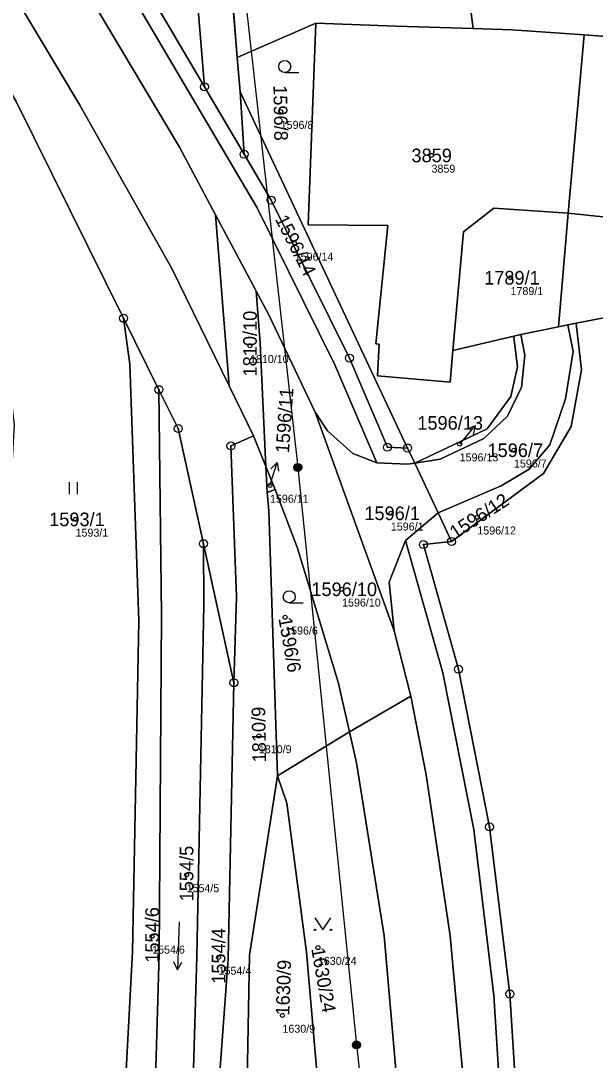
# Model space of a CAD drawing. Extents: x -653098 to -649479, y -997642 to -992666.
# Drawn here: x -650604.2 to -650532.3, y -996480.3 to -996350.3 of the extents above; entities that cross this region are included whole.
import ezdxf

# ---------------------------------------------------------------- set-up
doc = ezdxf.new("R2010")
doc.units = 0
for name, color, linetype in [('Definiční body', 7, 'Continuous'), ('Hranice parcel', 7, 'Continuous'), ('Parcelní čísla', 7, 'Continuous'), ('Polygon parcely', 7, 'Continuous'), ('Pop  PČ popisy', 7, 'Continuous'), ('Poz předměty', 7, 'Continuous'), ('Značky bodu BP', 7, 'Continuous'), ('Značky kultur', 7, 'Continuous')]:
    doc.layers.add(name, color=color, linetype=linetype)

msp = doc.modelspace()

# ---------------------------------------------------------------- linework, layer by layer
at = {"layer": 'Definiční body'}
for centre in [(-650571.66, -996361.69), (-650552.79, -996367.17), (-650569.9, -996378.16), (-650542.91, -996382.46), (-650575.5, -996390.96), (-650549.27, -996403.25), (-650542.48, -996404.02), (-650573, -996408.42), (-650597.32, -996412.66), (-650557.88, -996411.9), (-650547.06, -996412.39), (-650563.98, -996421.4), (-650571.1, -996424.9), (-650574.39, -996439.73), (-650583.43, -996457.1), (-650587.74, -996464.78), (-650567, -996466.19), (-650579.43, -996467.41), (-650571.44, -996474.67)]:
    msp.add_circle(centre, 0.25, dxfattribs=at)
at = {"layer": 'Hranice parcel'}
for p, q in [((-650554.94, -996294.79), (-650547.58, -996351.32)), ((-650581.76, -996297.58), (-650577.09, -996354.94)), ((-650587.29, -996348.25), (-650581.19, -996358.59)), ((-650567.26, -996350.65), (-650577.09, -996354.94)), ((-650533.69, -996352.11), (-650535.68, -996374.38)), ((-650533.69, -996352.11), (-650508.63, -996353.93)), ((-650577.09, -996354.94), (-650576.74, -996359.23)), ((-650581.19, -996358.59), (-650576.23, -996367.02)), ((-650576.23, -996367.02), (-650576.74, -996359.23)), ((-650576.74, -996359.23), (-650555.79, -996403.74)), ((-650578.11, -996395.96), (-650579.83, -996374.59)), ((-650536.9, -996388.58), (-650535.68, -996374.38)), ((-650535.68, -996374.38), (-650509.6, -996377.15)), ((-650586.89, -996396.45), (-650591.31, -996387.53)), ((-650535.73, -996388.34), (-650534.69, -996388.12)), ((-650536.9, -996388.58), (-650541.61, -996389.55)), ((-650535.73, -996388.34), (-650536.9, -996388.58)), ((-650542.51, -996389.75), (-650550.13, -996391.56)), ((-650542.51, -996389.75), (-650541.61, -996389.55)), ((-650578.11, -996395.96), (-650575.06, -996402.22)), ((-650567.34, -996399.26), (-650557.46, -996426.59)), ((-650575.06, -996402.22), (-650573.52, -996406.04)), ((-650555.79, -996403.74), (-650554.9, -996405.62)), ((-650573.52, -996406.04), (-650572.35, -996408.91)), ((-650573.52, -996406.04), (-650573.35, -996409.31)), ((-650551.97, -996411.84), (-650554.9, -996405.62)), ((-650572.35, -996408.91), (-650573.35, -996409.31)), ((-650556.03, -996415.31), (-650551.97, -996411.84)), ((-650550.29, -996415.42), (-650551.97, -996411.84)), ((-650581.32, -996415.7), (-650577.51, -996433.09)), ((-650555.4, -996434.75), (-650557.46, -996426.59)), ((-650555.4, -996434.75), (-650563.06, -996439.2)), ((-650572.05, -996444.71), (-650563.06, -996439.2))]:
    msp.add_line(p, q, dxfattribs=at)
for points in [[(-650575.37, -995959.87), (-650608.41, -995944), (-650610.43, -995943.86), (-650611.96, -995945.87), (-650628.76, -995975.13), (-650648.35, -996007.09), (-650662.99, -996034.56), (-650671.68, -996054.53), (-650676.6, -996068.37), (-650679.44, -996078.12), (-650683.79, -996097.9), (-650686.06, -996119.41), (-650686.27, -996132.3), (-650684.64, -996153.85), (-650680.81, -996173.83), (-650676.67, -996188.65), (-650668.33, -996210.53), (-650657.86, -996232.42), (-650644.24, -996256.86), (-650595.14, -996338.86), (-650574.61, -996373.71), (-650564.87, -996393.33), (-650559.65, -996405.6)], [(-650579.83, -996374.59), (-650584.33, -996366.13), (-650603.23, -996334.38), (-650640.77, -996271.85), (-650662.24, -996233.94), (-650673.04, -996211.24), (-650681.26, -996189.41), (-650687.35, -996165.84), (-650690.42, -996143.11), (-650690.64, -996118.19), (-650688.08, -996095.67), (-650683.42, -996075.21), (-650681.92, -996070.45)], [(-650591.31, -996387.53), (-650604.76, -996360.43), (-650648.92, -996285.46), (-650668.2, -996252.11), (-650678.11, -996231.78), (-650693.48, -996194.73), (-650701.11, -996158.83), (-650702.82, -996142.05), (-650703.55, -996130.09), (-650704.38, -996128.54)], [(-650699.56, -996129.85), (-650698.84, -996141.72), (-650697.15, -996158.23), (-650692.97, -996178.61), (-650686.91, -996198.66), (-650678.39, -996219.51), (-650663, -996249.61), (-650638.21, -996291.69), (-650596.8, -996360.89), (-650585.26, -996381.29), (-650578.11, -996395.96)], [(-650581.19, -996358.59), (-650582.63, -996340.7), (-650586.6, -996298.44)], [(-650550.13, -996391.56), (-650550.45, -996395.52), (-650559.53, -996394.71), (-650559.35, -996390.75), (-650559.75, -996390.72), (-650558.26, -996375.92), (-650568.24, -996375.83), (-650567.26, -996350.65)], [(-650567.26, -996350.65), (-650557.21, -996351.03), (-650547.58, -996351.32)], [(-650547.58, -996351.32), (-650542.76, -996351.46), (-650533.69, -996352.11)], [(-650576.23, -996367.02), (-650572.85, -996372.76), (-650563.06, -996392.5), (-650558.31, -996403.65), (-650555.79, -996403.74)], [(-650535.68, -996374.38), (-650545, -996373.74), (-650548.8, -996376.73), (-650550.13, -996391.56)], [(-650574.73, -996384.14), (-650574.86, -996383.9), (-650579.83, -996374.59)], [(-650567.34, -996399.26), (-650573.19, -996387.03), (-650574.73, -996384.14)], [(-650574.73, -996384.14), (-650574.23, -996390.63), (-650573.52, -996406.04)], [(-650503.13, -996383.96), (-650509.86, -996384.68), (-650526.23, -996386.52), (-650534.69, -996388.12)], [(-650589.96, -996512.9), (-650591.82, -996502.17), (-650591.18, -996485.47), (-650590.2, -996466.72), (-650589.41, -996425.36), (-650590.51, -996393.26), (-650591.31, -996387.53)], [(-650534.69, -996388.12), (-650534.68, -996388.19), (-650534.04, -996393.96), (-650535.34, -996401.04), (-650538.78, -996406.94), (-650550.29, -996415.42)], [(-650551.97, -996411.84), (-650544.07, -996408.48), (-650540.59, -996406.37), (-650538, -996403.35), (-650536.05, -996397.61), (-650535.09, -996391.66), (-650535.73, -996388.34)], [(-650541.61, -996389.55), (-650541.11, -996392.13), (-650541.55, -996396.13), (-650543.3, -996399.74), (-650546.25, -996402.55), (-650551.7, -996405.13), (-650554.9, -996405.62)], [(-650554.9, -996405.62), (-650545.84, -996401.35), (-650542.89, -996397.32), (-650542.03, -996393.59), (-650542.49, -996389.9), (-650542.51, -996389.75)], [(-650586.89, -996396.45), (-650586.55, -996424.66), (-650586.84, -996466.96), (-650587.38, -996484.09), (-650588.2, -996502.26), (-650589.96, -996512.9)], [(-650581.32, -996415.7), (-650584.47, -996401.31), (-650586.89, -996396.45)], [(-650559.65, -996405.6), (-650562.63, -996404.44), (-650565.79, -996401.6), (-650567.34, -996399.26)], [(-650575.06, -996402.22), (-650577.88, -996403.47), (-650577.18, -996422.36), (-650577.51, -996433.09)], [(-650554.9, -996405.62), (-650555.81, -996405.74), (-650559.65, -996405.6)], [(-650563.06, -996439.2), (-650564.47, -996432.99), (-650569.57, -996416.28), (-650572.35, -996408.91)], [(-650573.35, -996409.31), (-650573.16, -996411.6), (-650572.05, -996444.71)], [(-650557.46, -996426.59), (-650558.07, -996420.5), (-650556.03, -996415.31)], [(-650481.95, -996618.06), (-650484.99, -996623.94), (-650491.46, -996628.69), (-650497.3, -996630.15), (-650503.13, -996629.04), (-650508.23, -996625.8), (-650513.58, -996619.75), (-650516.18, -996615.43), (-650526.52, -996590.48), (-650532.31, -996579.92), (-650535.84, -996568.82), (-650536.89, -996564.24), (-650538.64, -996553.86), (-650541.82, -996522.77), (-650544.98, -996472.17), (-650547.51, -996451.42), (-650551.36, -996431.86), (-650556.03, -996415.31)], [(-650550.29, -996415.42), (-650553.81, -996415.81), (-650549.42, -996431.4), (-650545.54, -996451.11), (-650542.99, -996471.99), (-650539.83, -996522.62), (-650536.66, -996553.58), (-650533.9, -996568.33), (-650530.47, -996579.13), (-650524.71, -996589.62), (-650514.09, -996615.3), (-650481.83, -996615.01)], [(-650587.45, -996520.47), (-650586.14, -996517.22), (-650583.65, -996508.75), (-650583.07, -996498.11), (-650582.16, -996467.3), (-650581.26, -996423.36), (-650581.32, -996415.7)], [(-650577.51, -996433.09), (-650578.22, -996467.58), (-650580.47, -996498.26), (-650580.71, -996502.46), (-650580.86, -996508.82), (-650581.91, -996521.13)], [(-650515.19, -996635.92), (-650515.74, -996634.98), (-650521.36, -996615.63), (-650527.52, -996600.48), (-650530.39, -996592.62), (-650536.34, -996584.16), (-650536.75, -996582.96), (-650541.65, -996564.02), (-650544.65, -996544.52), (-650546.28, -996524.74), (-650547.43, -996504.82), (-650548.64, -996484.79), (-650550.46, -996464.7), (-650553.47, -996444.6), (-650555.4, -996434.75)], [(-650563.06, -996439.2), (-650562.17, -996443.09), (-650558.72, -996464.73), (-650556.36, -996491.5)], [(-650572.05, -996444.71), (-650575.58, -996467.15), (-650575.92, -996487.33), (-650576.13, -996490.32)], [(-650566.65, -996490.88), (-650566.73, -996487.87), (-650566.77, -996486.05), (-650568.45, -996466.75), (-650570.87, -996448.12), (-650572.05, -996444.71)]]:
    msp.add_lwpolyline(points, dxfattribs=at)
at = {"layer": 'Polygon parcely'}
for points in [[(-650599.51, -996170.83), (-650604.08, -996171.11), (-650601.43, -996187.33), (-650590.92, -996299.38), (-650588.21, -996340.7), (-650587.29, -996348.25), (-650581.19, -996358.59), (-650582.63, -996340.7), (-650586.6, -996298.44), (-650597.07, -996187.91)], [(-650547.58, -996351.32), (-650554.94, -996294.79), (-650581.76, -996297.58), (-650577.09, -996354.94), (-650567.26, -996350.65), (-650557.21, -996351.03)], [(-650542.76, -996351.46), (-650533.69, -996352.11), (-650508.63, -996353.93), (-650551.45, -996299.47), (-650554.94, -996294.79), (-650547.58, -996351.32)], [(-650576.23, -996367.02), (-650576.74, -996359.23), (-650577.09, -996354.94), (-650581.76, -996297.58), (-650586.6, -996298.44), (-650582.63, -996340.7), (-650581.19, -996358.59)], [(-650542.49, -996389.9), (-650542.51, -996389.75), (-650550.13, -996391.56), (-650550.45, -996395.52), (-650559.53, -996394.71), (-650559.35, -996390.75), (-650559.75, -996390.72), (-650558.26, -996375.92), (-650568.24, -996375.83), (-650567.26, -996350.65), (-650577.09, -996354.94), (-650576.74, -996359.23), (-650555.79, -996403.74), (-650554.9, -996405.62), (-650545.84, -996401.35), (-650542.89, -996397.32), (-650542.03, -996393.59)], [(-650547.58, -996351.32), (-650557.21, -996351.03), (-650567.26, -996350.65), (-650568.24, -996375.83), (-650558.26, -996375.92), (-650559.75, -996390.72), (-650559.35, -996390.75), (-650559.53, -996394.71), (-650550.45, -996395.52), (-650550.13, -996391.56), (-650548.8, -996376.73), (-650545, -996373.74), (-650535.68, -996374.38), (-650533.69, -996352.11), (-650542.76, -996351.46)], [(-650509.6, -996377.15), (-650508.63, -996353.93), (-650533.69, -996352.11), (-650535.68, -996374.38)], [(-650534.69, -996388.12), (-650526.23, -996386.52), (-650509.86, -996384.68), (-650503.13, -996383.96), (-650483.36, -996381.86), (-650449.54, -996376.52), (-650448.6, -996369.71), (-650449.42, -996356.46), (-650463.33, -996369.25), (-650484.06, -996375.37), (-650502.17, -996376.51), (-650506.12, -996376.78), (-650509.6, -996377.15), (-650535.68, -996374.38), (-650536.9, -996388.58), (-650535.73, -996388.34)], [(-650576.23, -996367.02), (-650572.85, -996372.76), (-650563.06, -996392.5), (-650558.31, -996403.65), (-650555.79, -996403.74), (-650576.74, -996359.23)], [(-650541.61, -996389.55), (-650536.9, -996388.58), (-650535.68, -996374.38), (-650545, -996373.74), (-650548.8, -996376.73), (-650550.13, -996391.56), (-650542.51, -996389.75)], [(-650575.06, -996402.22), (-650573.52, -996406.04), (-650574.23, -996390.63), (-650574.73, -996384.14), (-650574.86, -996383.9), (-650579.83, -996374.59), (-650578.11, -996395.96)], [(-650574.73, -996384.14), (-650574.23, -996390.63), (-650573.52, -996406.04), (-650572.35, -996408.91), (-650569.57, -996416.28), (-650564.47, -996432.99), (-650563.06, -996439.2), (-650555.4, -996434.75), (-650557.46, -996426.59), (-650567.34, -996399.26), (-650573.19, -996387.03)], [(-650591.31, -996387.53), (-650590.51, -996393.26), (-650589.41, -996425.36), (-650590.2, -996466.72), (-650591.18, -996485.47), (-650591.82, -996502.17), (-650589.96, -996512.9), (-650588.2, -996502.26), (-650587.38, -996484.09), (-650586.84, -996466.96), (-650586.55, -996424.66), (-650586.89, -996396.45)], [(-650551.97, -996411.84), (-650550.29, -996415.42), (-650538.78, -996406.94), (-650535.34, -996401.04), (-650534.04, -996393.96), (-650534.68, -996388.19), (-650534.69, -996388.12), (-650535.73, -996388.34), (-650535.09, -996391.66), (-650536.05, -996397.61), (-650538, -996403.35), (-650540.59, -996406.37), (-650544.07, -996408.48)], [(-650535.73, -996388.34), (-650536.9, -996388.58), (-650541.61, -996389.55), (-650541.11, -996392.13), (-650541.55, -996396.13), (-650543.3, -996399.74), (-650546.25, -996402.55), (-650551.7, -996405.13), (-650554.9, -996405.62), (-650551.97, -996411.84), (-650544.07, -996408.48), (-650540.59, -996406.37), (-650538, -996403.35), (-650536.05, -996397.61), (-650535.09, -996391.66)], [(-650541.61, -996389.55), (-650542.51, -996389.75), (-650542.49, -996389.9), (-650542.03, -996393.59), (-650542.89, -996397.32), (-650545.84, -996401.35), (-650554.9, -996405.62), (-650551.7, -996405.13), (-650546.25, -996402.55), (-650543.3, -996399.74), (-650541.55, -996396.13), (-650541.11, -996392.13)], [(-650583.65, -996508.75), (-650583.07, -996498.11), (-650582.16, -996467.3), (-650581.26, -996423.36), (-650581.32, -996415.7), (-650584.47, -996401.31), (-650586.89, -996396.45), (-650586.55, -996424.66), (-650586.84, -996466.96), (-650587.38, -996484.09), (-650588.2, -996502.26), (-650589.96, -996512.9), (-650606.14, -996543.16), (-650606.53, -996546.22), (-650599.96, -996558.72), (-650590.92, -996529.08), (-650587.45, -996520.47), (-650586.14, -996517.22)], [(-650557.46, -996426.59), (-650558.07, -996420.5), (-650556.03, -996415.31), (-650551.97, -996411.84), (-650554.9, -996405.62), (-650555.81, -996405.74), (-650559.65, -996405.6), (-650562.63, -996404.44), (-650565.79, -996401.6), (-650567.34, -996399.26)], [(-650573.52, -996406.04), (-650573.35, -996409.31), (-650572.35, -996408.91)], [(-650573.16, -996411.6), (-650572.05, -996444.71), (-650563.06, -996439.2), (-650564.47, -996432.99), (-650569.57, -996416.28), (-650572.35, -996408.91), (-650573.35, -996409.31)], [(-650581.91, -996521.13), (-650580.86, -996508.82), (-650580.71, -996502.46), (-650580.47, -996498.26), (-650578.22, -996467.58), (-650577.51, -996433.09), (-650581.32, -996415.7), (-650581.26, -996423.36), (-650582.16, -996467.3), (-650583.07, -996498.11), (-650583.65, -996508.75), (-650586.14, -996517.22), (-650587.45, -996520.47)], [(-650572.05, -996444.71), (-650570.87, -996448.12), (-650568.45, -996466.75), (-650566.77, -996486.05), (-650566.73, -996487.87), (-650566.65, -996490.88), (-650556.36, -996491.5), (-650558.72, -996464.73), (-650562.17, -996443.09), (-650563.06, -996439.2)], [(-650575.58, -996467.15), (-650575.92, -996487.33), (-650576.13, -996490.32), (-650566.65, -996490.88), (-650566.73, -996487.87), (-650566.77, -996486.05), (-650568.45, -996466.75), (-650570.87, -996448.12), (-650572.05, -996444.71)]]:
    msp.add_lwpolyline(points, close=True, dxfattribs=at)
for points in [[(-650632.09, -996321.67), (-650614.12, -996355.56), (-650607.05, -996384.1), (-650604.98, -996400.86), (-650606.16, -996421.63), (-650611.29, -996449.19), (-650617.21, -996488.51), (-650616.51, -996503.94), (-650615.64, -996515.14), (-650594.33, -996512.62), (-650589.96, -996512.9), (-650591.82, -996502.17), (-650591.18, -996485.47), (-650590.2, -996466.72), (-650589.41, -996425.36), (-650590.51, -996393.26), (-650591.31, -996387.53), (-650604.76, -996360.43), (-650648.92, -996285.46)], [(-650648.92, -996285.46), (-650604.76, -996360.43), (-650591.31, -996387.53), (-650586.89, -996396.45), (-650584.47, -996401.31), (-650581.32, -996415.7), (-650577.51, -996433.09), (-650577.18, -996422.36), (-650577.88, -996403.47), (-650575.06, -996402.22), (-650578.11, -996395.96), (-650585.26, -996381.29), (-650596.8, -996360.89), (-650638.21, -996291.69)], [(-650638.21, -996291.69), (-650596.8, -996360.89), (-650585.26, -996381.29), (-650578.11, -996395.96), (-650579.83, -996374.59), (-650584.33, -996366.13), (-650603.23, -996334.38)], [(-650603.23, -996334.38), (-650584.33, -996366.13), (-650579.83, -996374.59), (-650574.86, -996383.9), (-650574.73, -996384.14), (-650573.19, -996387.03), (-650567.34, -996399.26), (-650565.79, -996401.6), (-650562.63, -996404.44), (-650559.65, -996405.6), (-650564.87, -996393.33), (-650574.61, -996373.71), (-650595.14, -996338.86)], [(-650595.14, -996338.86), (-650574.61, -996373.71), (-650564.87, -996393.33), (-650559.65, -996405.6), (-650555.81, -996405.74), (-650554.9, -996405.62), (-650555.79, -996403.74), (-650558.31, -996403.65), (-650563.06, -996392.5), (-650572.85, -996372.76), (-650576.23, -996367.02), (-650581.19, -996358.59), (-650587.29, -996348.25)], [(-650526.23, -996386.52), (-650534.69, -996388.12), (-650534.68, -996388.19), (-650534.04, -996393.96), (-650535.34, -996401.04), (-650538.78, -996406.94), (-650550.29, -996415.42), (-650553.81, -996415.81), (-650549.42, -996431.4), (-650545.54, -996451.11), (-650542.99, -996471.99), (-650539.83, -996522.62), (-650536.66, -996553.58), (-650533.9, -996568.33)], [(-650575.92, -996487.33), (-650575.58, -996467.15), (-650572.05, -996444.71), (-650573.16, -996411.6), (-650573.35, -996409.31), (-650573.52, -996406.04), (-650575.06, -996402.22), (-650577.88, -996403.47), (-650577.18, -996422.36), (-650577.51, -996433.09), (-650578.22, -996467.58), (-650580.47, -996498.26)], [(-650533.9, -996568.33), (-650536.66, -996553.58), (-650539.83, -996522.62), (-650542.99, -996471.99), (-650545.54, -996451.11), (-650549.42, -996431.4), (-650553.81, -996415.81), (-650550.29, -996415.42), (-650551.97, -996411.84), (-650556.03, -996415.31), (-650551.36, -996431.86), (-650547.51, -996451.42), (-650544.98, -996472.17), (-650541.82, -996522.77), (-650538.64, -996553.86), (-650536.89, -996564.24), (-650535.84, -996568.82)], [(-650535.84, -996568.82), (-650536.89, -996564.24), (-650538.64, -996553.86), (-650541.82, -996522.77), (-650544.98, -996472.17), (-650547.51, -996451.42), (-650551.36, -996431.86), (-650556.03, -996415.31), (-650558.07, -996420.5), (-650557.46, -996426.59), (-650555.4, -996434.75), (-650553.47, -996444.6), (-650550.46, -996464.7), (-650548.64, -996484.79), (-650547.43, -996504.82), (-650546.28, -996524.74), (-650544.65, -996544.52), (-650541.65, -996564.02), (-650536.75, -996582.96)], [(-650536.75, -996582.96), (-650541.65, -996564.02), (-650544.65, -996544.52), (-650546.28, -996524.74), (-650547.43, -996504.82), (-650548.64, -996484.79), (-650550.46, -996464.7), (-650553.47, -996444.6), (-650555.4, -996434.75), (-650563.06, -996439.2), (-650562.17, -996443.09), (-650558.72, -996464.73), (-650556.36, -996491.5), (-650554.43, -996524.57), (-650552.38, -996548.84), (-650549.17, -996572.98)]]:
    msp.add_lwpolyline(points, dxfattribs=at)
at = {"layer": 'Pop  PČ popisy'}
for p, q in [((-650549.27, -996403.25), (-650547.34, -996400.95)), ((-650547.34, -996400.95), (-650548.37, -996401.4)), ((-650547.34, -996400.95), (-650547.6, -996402.04)), ((-650573, -996408.42), (-650572.12, -996405.55)), ((-650572.12, -996405.55), (-650572.89, -996406.36)), ((-650572.12, -996405.55), (-650571.94, -996406.65))]:
    msp.add_line(p, q, dxfattribs=at)
at = {"layer": 'Poz předměty'}
for p, q in [((-650577.17, -996338.07), (-650569.52, -996406.17)), ((-650569.52, -996406.17), (-650562.19, -996478.36)), ((-650562.19, -996478.36), (-650554.07, -996548.07))]:
    msp.add_line(p, q, dxfattribs=at)
for centre, radius in [((-650569.52, -996406.17), 0.5), ((-650569.52, -996406.17), 0.4), ((-650569.52, -996406.17), 0.3), ((-650569.52, -996406.17), 0.2), ((-650569.52, -996406.17), 0.1), ((-650562.19, -996478.36), 0.5), ((-650562.19, -996478.36), 0.4), ((-650562.19, -996478.36), 0.3), ((-650562.19, -996478.36), 0.2), ((-650562.19, -996478.36), 0.1)]:
    msp.add_circle(centre, radius, dxfattribs=at)
at = {"layer": 'Značky bodu BP'}
for centre, radius in [((-650581.19, -996358.59), 0.5), ((-650581.19, -996358.59), 0.0303), ((-650576.23, -996367.02), 0.5), ((-650576.23, -996367.02), 0.0303), ((-650572.85, -996372.76), 0.5), ((-650572.85, -996372.76), 0.0303), ((-650591.31, -996387.53), 0.5), ((-650591.31, -996387.53), 0.0303), ((-650563.06, -996392.5), 0.5), ((-650563.06, -996392.5), 0.0303), ((-650586.89, -996396.45), 0.5), ((-650586.89, -996396.45), 0.0303), ((-650584.47, -996401.31), 0.5), ((-650584.47, -996401.31), 0.0303), ((-650577.88, -996403.47), 0.5), ((-650577.88, -996403.47), 0.0303), ((-650558.31, -996403.65), 0.5), ((-650558.31, -996403.65), 0.0303), ((-650555.79, -996403.74), 0.5), ((-650555.79, -996403.74), 0.0303), ((-650581.32, -996415.7), 0.5), ((-650553.81, -996415.81), 0.5), ((-650550.29, -996415.42), 0.5), ((-650550.29, -996415.42), 0.0303), ((-650581.32, -996415.7), 0.0303), ((-650553.81, -996415.81), 0.0303), ((-650549.42, -996431.4), 0.5), ((-650549.42, -996431.4), 0.0303), ((-650577.51, -996433.09), 0.5), ((-650577.51, -996433.09), 0.0303), ((-650545.54, -996451.11), 0.5), ((-650545.54, -996451.11), 0.0303), ((-650542.99, -996471.99), 0.5), ((-650542.99, -996471.99), 0.0303)]:
    msp.add_circle(centre, radius, dxfattribs=at)
at = {"layer": 'Značky kultur'}
for p, q in [((-650571.15, -996356.8), (-650569.4, -996356.8)), ((-650598.06, -996409.51), (-650598.06, -996408.01)), ((-650597.06, -996409.51), (-650597.06, -996408.01)), ((-650570.59, -996423.08), (-650568.84, -996423.08)), ((-650584.36, -996462.96), (-650584.57, -996468.96)), ((-650584.57, -996468.96), (-650585.04, -996467.96)), ((-650584.57, -996468.96), (-650584.04, -996468))]:
    msp.add_line(p, q, dxfattribs=at)
msp.add_lwpolyline([(-650567.37, -996462.47), (-650566.37, -996463.97), (-650565.37, -996462.47)], dxfattribs=at)
for centre, radius in [((-650571.15, -996356.05), 0.75), ((-650570.59, -996422.33), 0.75), ((-650567.37, -996463.97), 0.1), ((-650565.37, -996463.97), 0.1)]:
    msp.add_circle(centre, radius, dxfattribs=at)

# ---------------------------------------------------------------- texts
at = {"layer": 'Definiční body'}
for s, p in [('1596/8', (-650571.66, -996363.85)), ('3859', (-650552.79, -996369.33)), ('1596/14', (-650569.9, -996380.32)), ('1789/1', (-650542.91, -996384.62)), ('1810/10', (-650575.5, -996393.12)), ('1596/13', (-650549.27, -996405.41)), ('1596/7', (-650542.48, -996406.18)), ('1596/11', (-650573, -996410.58)), ('1593/1', (-650597.32, -996414.82)), ('1596/1', (-650557.88, -996414.06)), ('1596/12', (-650547.06, -996414.55)), ('1596/10', (-650563.98, -996423.56)), ('1596/6', (-650571.1, -996427.06)), ('1810/9', (-650574.39, -996441.89)), ('1554/5', (-650583.43, -996459.26)), ('1554/6', (-650587.74, -996466.94)), ('1630/24', (-650567, -996468.35)), ('1554/4', (-650579.43, -996469.57)), ('1630/9', (-650571.44, -996476.83))]:
    msp.add_text(s, height=1, dxfattribs=at).set_placement(p)
at = {"layer": 'Parcelní čísla'}
for s, rotation, p in [('1596/8', 271, (-650572.57, -996358.4)), ('1596/14', 297, (-650572.4, -996375.13)), ('1810/10', 90, (-650574.65, -996394.8)), ('1596/11', 86, (-650570.62, -996404.44)), ('1596/12', 33, (-650549.82, -996415.19)), ('1596/6', 280, (-650571.94, -996425.05)), ('1810/9', 91, (-650573.48, -996443.02)), ('1554/5', 90, (-650582.58, -996460.41)), ('1554/6', 90, (-650586.89, -996468.08)), ('1554/4', 90, (-650578.58, -996470.71)), ('1630/24', 280, (-650567.84, -996466.34)), ('1630/9', 88, (-650570.59, -996474.7))]:
    msp.add_text(s, height=1.7, rotation=rotation, dxfattribs=at).set_placement(p)
for s, p in [('3859', (-650555.3, -996368.02)), ('1789/1', (-650546.21, -996383.31)), ('1596/13', (-650554.57, -996401.45)), ('1596/7', (-650545.79, -996404.87)), ('1596/1', (-650561.19, -996412.75)), ('1593/1', (-650600.62, -996413.51)), ('1596/10', (-650567.82, -996422.25))]:
    msp.add_text(s, height=1.7, dxfattribs=at).set_placement(p)

doc.saveas('drawing.dxf')
